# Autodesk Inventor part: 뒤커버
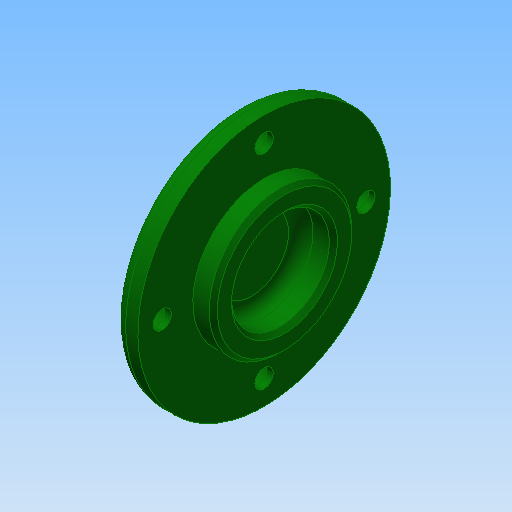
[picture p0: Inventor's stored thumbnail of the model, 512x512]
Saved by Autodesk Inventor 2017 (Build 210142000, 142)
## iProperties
Created: 2015-12
Part Number: 뒤커버
Document SubType Name: Modeling
Designer: mdu
Density: 2.71 g/cm^3
Material: 알루미늄 6061
Appearance: 진녹색
Mass: 56.2003 g
Surface Area: 84.0408 cm^2
Volume: 20.7381 cm^3
Author: mdu
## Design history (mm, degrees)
sketch "스케치1"
  geometry: L1 (-7, 0)-(7, 0); L2 (-7, 0)-(-7, 15.539); L3 (-7, 15.539)-(-4, 18.5); L4 (-4, 18.5)-(-4, 31); L5 (-4, 31)-(2, 31); L6 (2, 31)-(2, 17.5); L7 (2, 17.5)-(7, 17.5); L8 (7, 17.5)-(7, 0); 2 further points
  constraints: 16 end point, 4 parallel, 2 perpendicular, 1 coincident, 1 horizontal, 1 midpoint
  dimensions: "d0" = 14 distance of L1.start L1.end; "d1" = 62 diameter of L5 L1; "d2" = 35 diameter of L7 L1; "d3" = 37 diameter of L3.end L1; "d4" = 3 distance between parallel lines of L4 L2; "d5" = 6 distance of L4.end L5.end
revolve "회전1" sketch "스케치1" stored, may be unused: angle "d6" = 90 deg
sketch "스케치2" dims "d32" = 50
  geometry: 3 further points
  constraints: 2 vertical alignment, 1 coincident, 2 other
hole "구멍1" sketch "스케치2" at (0, 25) diameter "d8" = 4.5; stored, may be unused: countersink angle "d12" = 90 deg, drill point angle "d14" = 118 deg; dims "d9" = 6, "d10" = 8, "d11" = 4.4, "d13" = 8
hole "구멍2" diameter "d20" = 24; stored, may be unused: countersink angle "d24" = 90 deg, drill point angle "d26" = 0 deg; dims "d18" = 10, "d19" = 10, "d21" = 6, "d22" = 8, "d23" = 4.4, "d25" = 8
fillet "모깎기1" dims "d27" = 3
fillet "모깎기2" dims "d28" = 3
chamfer "모따기1" distance "d29" = 1; stored, may be unused: second distance "d30" = 2, angle "d31" = 45 deg
node "솔리드1"
pattern_circular "원형 패턴1" dims angle "d16" = 360 deg
